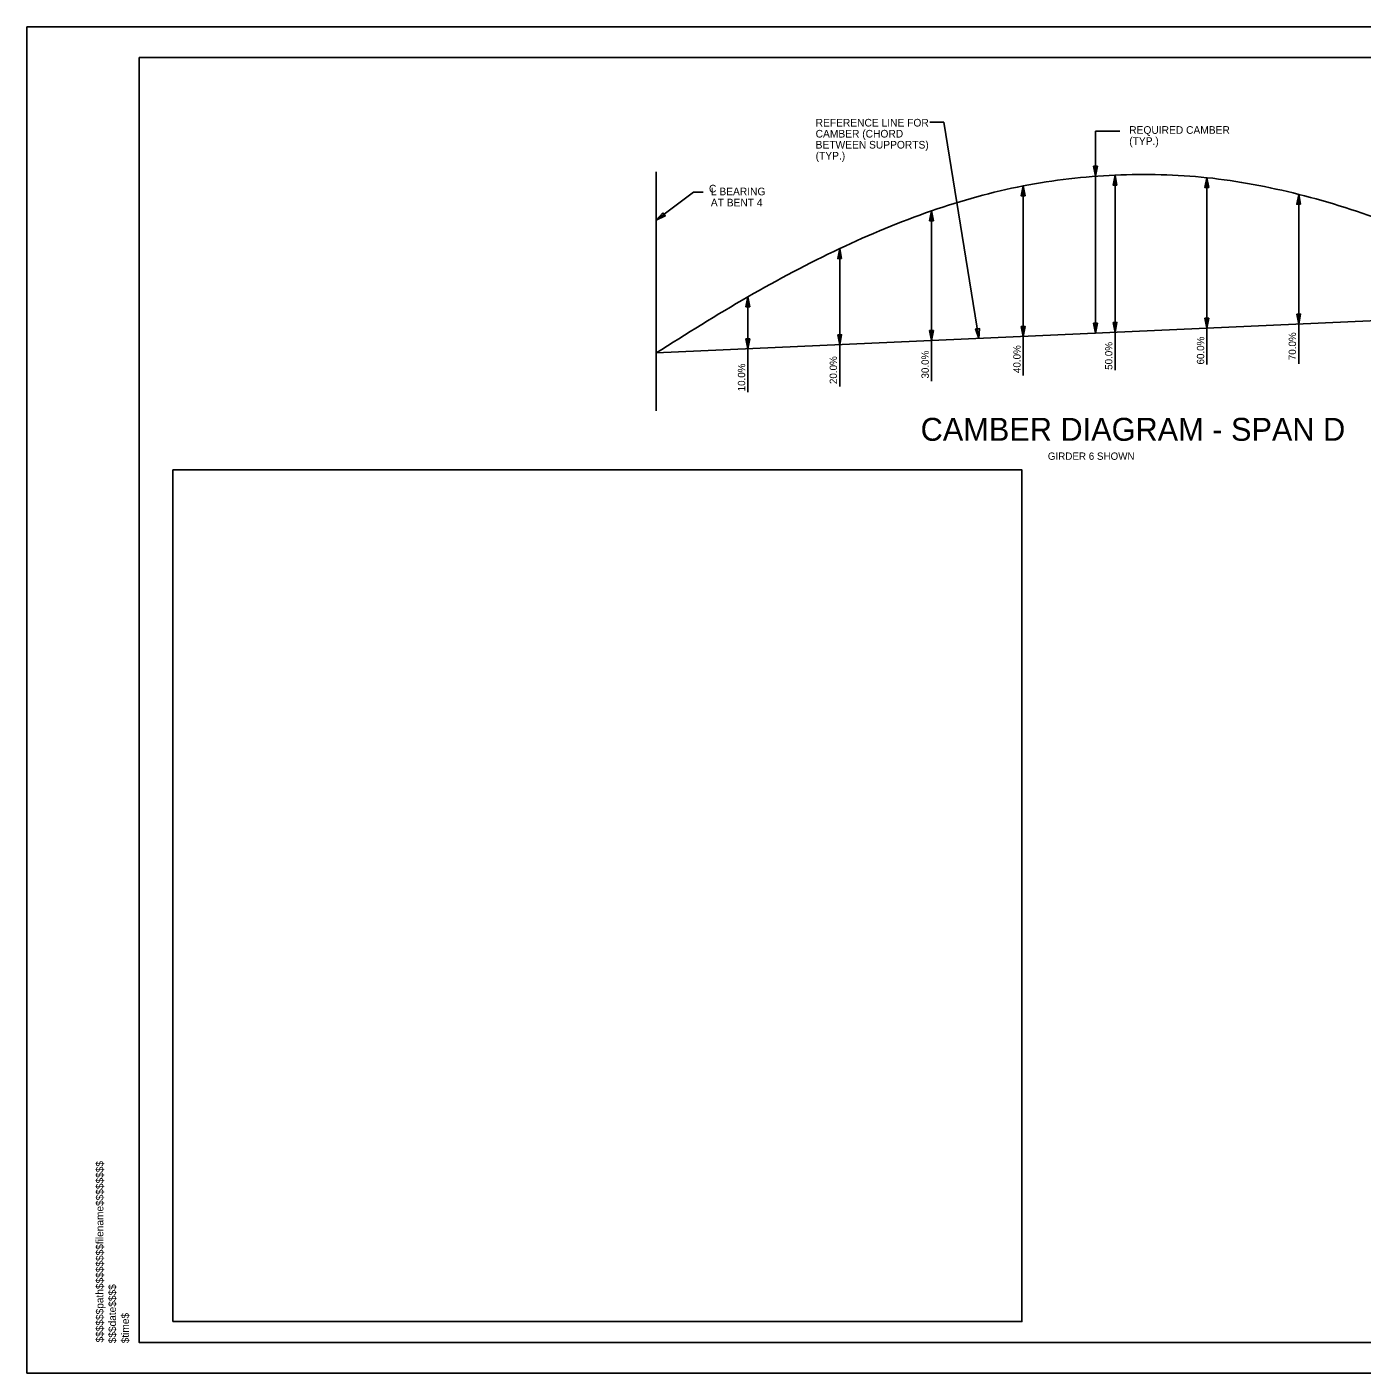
# Model space of a CAD drawing. Extents: x -125.5 to -89.4, y -5.1 to 16.9.
# Drawn here: x -125.53 to -103.72, y -5.07 to 16.93 of the extents above; entities that cross this region are included whole.
import ezdxf

# ---------------------------------------------------------------- set-up
doc = ezdxf.new("R2010")
doc.units = 0
for name, color, linetype in [('BR_AUTO DIMENSION', 7, 'Continuous'), ('BR_BORDER LINES', 7, 'Continuous'), ('BR_CENTER LINES', 7, 'Continuous'), ('BR_TABLE LINES', 7, 'Continuous'), ('BR_TEXT', 7, 'Continuous'), ('Level 31', 7, 'Continuous'), ('RD_SHT_ID', 7, 'Continuous')]:
    doc.layers.add(name, color=color, linetype=linetype)

msp = doc.modelspace()

# ---------------------------------------------------------------- linework, layer by layer
at = {"layer": 'BR_AUTO DIMENSION'}
for p, q in [((-110.779, 15.379), (-110.549, 15.379)), ((-110.549, 15.379), (-109.981, 11.842)), ((-108.075, 11.928), (-108.075, 15.231)), ((-108.075, 15.231), (-107.673, 15.231)), ((-114.641, 14.234), (-115.253, 13.776)), ((-114.481, 14.234), (-114.641, 14.234))]:
    msp.add_line(p, q, dxfattribs=at)
for points in [[(-108.106, 14.656), (-108.075, 14.493), (-108.043, 14.656)], [(-109.222, 14.172), (-109.253, 14.335), (-109.285, 14.172)], [(-107.722, 14.35), (-107.753, 14.512), (-107.785, 14.35)], [(-106.222, 14.307), (-106.253, 14.47), (-106.285, 14.307)], [(-104.722, 14.035), (-104.753, 14.197), (-104.785, 14.035)], [(-115.141, 13.897), (-115.253, 13.776), (-115.104, 13.846)], [(-110.722, 13.765), (-110.753, 13.927), (-110.785, 13.765)], [(-112.222, 13.147), (-112.253, 13.31), (-112.285, 13.147)], [(-113.722, 12.36), (-113.753, 12.522), (-113.785, 12.36)], [(-107.785, 12.105), (-107.753, 11.942), (-107.722, 12.105)], [(-106.285, 12.172), (-106.253, 12.01), (-106.222, 12.172)], [(-104.785, 12.24), (-104.753, 12.077), (-104.722, 12.24)], [(-112.285, 11.902), (-112.253, 11.74), (-112.222, 11.902)], [(-110.785, 11.97), (-110.753, 11.807), (-110.722, 11.97)], [(-110.033, 11.999), (-109.981, 11.842), (-109.971, 12.007)], [(-109.285, 12.037), (-109.253, 11.875), (-109.222, 12.037)], [(-108.106, 12.09), (-108.075, 11.928), (-108.043, 12.09)], [(-113.785, 11.835), (-113.753, 11.672), (-113.722, 11.835)]]:
    msp.add_lwpolyline(points, close=True, dxfattribs=at)
at = {"layer": 'BR_BORDER LINES'}
for p, q in [((-90.033, 16.434), (-123.699, 16.434)), ((-123.699, -4.566), (-123.699, 16.434)), ((-123.699, -4.566), (-90.033, -4.566))]:
    msp.add_line(p, q, dxfattribs=at)
at = {"layer": 'BR_CENTER LINES'}
msp.add_line((-115.253, 10.659), (-115.253, 14.566), dxfattribs=at)
at = {"layer": 'BR_TABLE LINES'}
for p, q in [((-109.253, 11.236), (-109.253, 14.335)), ((-107.753, 11.326), (-107.753, 14.512)), ((-106.253, 11.416), (-106.253, 14.47)), ((-104.753, 11.426), (-104.753, 14.197)), ((-110.753, 11.146), (-110.753, 13.927)), ((-112.253, 11.056), (-112.253, 13.31)), ((-113.753, 10.966), (-113.753, 12.522)), ((-100.257, 12.28), (-115.253, 11.605))]:
    msp.add_line(p, q, dxfattribs=at)
for points in [[(-123.699, 16.434), (-90.033, 16.434), (-90.033, -4.566), (-123.699, -4.566)], [(-123.148, -4.224), (-109.276, -4.224), (-109.276, 9.695), (-123.148, 9.695)]]:
    msp.add_lwpolyline(points, close=True, dxfattribs=at)
msp.add_spline([(-115.253, 11.605), (-113.753, 12.522), (-112.253, 13.31), (-110.753, 13.927), (-109.253, 14.335), (-107.753, 14.512), (-106.253, 14.47), (-104.753, 14.197), (-103.253, 13.725), (-101.753, 13.072), (-100.257, 12.28)], degree=3, dxfattribs=at)
at = {"layer": 'Level 31'}
msp.add_lwpolyline([(-125.533, -5.066), (-89.533, -5.066), (-89.533, 16.934), (-125.533, 16.934)], close=True, dxfattribs=at)

# ---------------------------------------------------------------- texts
at = {"layer": 'BR_AUTO DIMENSION'}
for s, p in [('REFERENCE LINE FOR', (-112.646, 15.306)), ('CAMBER (CHORD', (-112.646, 15.126)), ('REQUIRED CAMBER', (-107.522, 15.187)), ('BETWEEN SUPPORTS)', (-112.646, 14.946)), ('(TYP.)', (-107.522, 15.006)), ('(TYP.)', (-112.646, 14.766)), ('C', (-114.389, 14.229)), ('L BEARING', (-114.358, 14.182)), ('AT BENT 4', (-114.358, 14.001))]:
    msp.add_text(s, height=0.125, dxfattribs=at).set_placement(p)
at = {"layer": 'BR_TEXT'}
for s, p in [('70.0%', (-104.797, 11.487)), ('40.0%', (-109.297, 11.277)), ('50.0%', (-107.797, 11.33)), ('60.0%', (-106.297, 11.417)), ('20.0%', (-112.297, 11.097)), ('30.0%', (-110.797, 11.187)), ('10.0%', (-113.797, 10.978))]:
    msp.add_text(s, height=0.12, rotation=90, dxfattribs=at).set_placement(p)
for s, height, p in [('CAMBER DIAGRAM - SPAN D', 0.375, (-110.93, 10.17)), ('GIRDER 6 SHOWN', 0.12, (-108.852, 9.859))]:
    msp.add_text(s, height=height, dxfattribs=at).set_placement(p)
at = {"layer": 'RD_SHT_ID'}
for s, height, p in [('$$$$$$path$$$$$$$$filename$$$$$$$$', 0.12347, (-124.283, -4.566)), ('$$$date$$$$', 0.12347, (-124.077, -4.579)), ('$time$', 0.1235, (-123.866, -4.579))]:
    msp.add_text(s, height=height, rotation=90, dxfattribs=at).set_placement(p)

doc.saveas('drawing.dxf')
